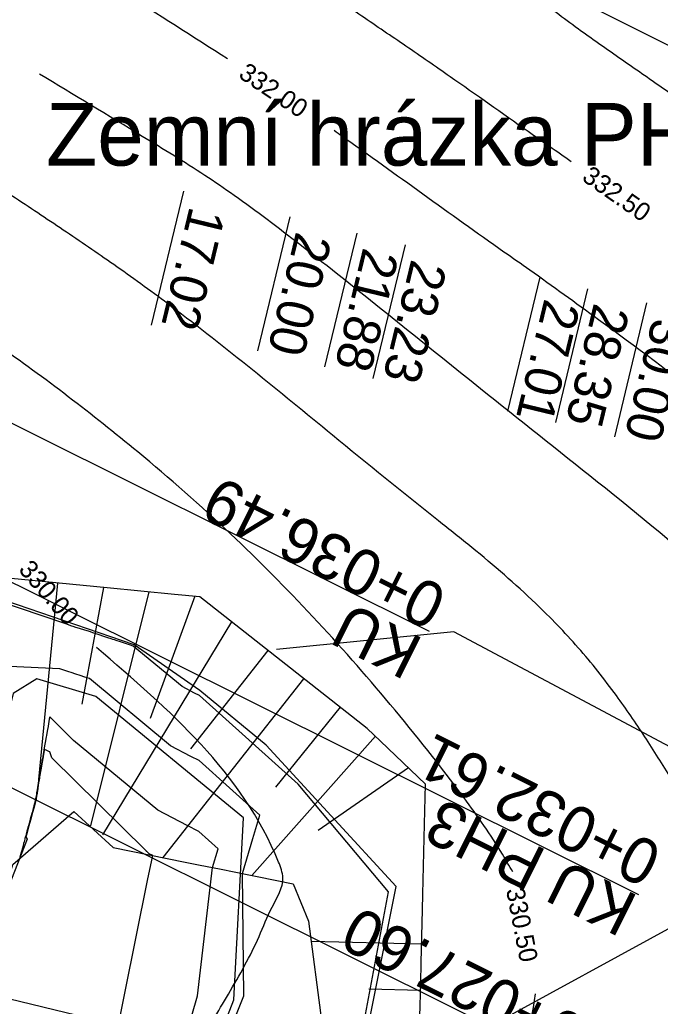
# Model space of a CAD drawing. Extents: x -564043 to -563833, y -1163561 to -1163412.
# Drawn here: x -563886.88 to -563869.43, y -1163493.12 to -1163466.24 of the extents above; entities that cross this region are included whole.
import ezdxf

# ---------------------------------------------------------------- set-up
doc = ezdxf.new("R2010")
doc.units = 0
for name, color, linetype in [('4', 7, 'Continuous'), ('5', 7, 'Continuous'), ('_popis staničení PH3', 7, 'Continuous'), ('_popis staničení T3', 7, 'Continuous'), ('Default', 7, 'Continuous'), ('Line', 7, 'Continuous'), ('Obvod PU', 7, 'Continuous'), ('Vrstva 24', 7, 'Continuous'), ('Vrstva 25', 7, 'Continuous'), ('Vrstva 26', 7, 'Continuous')]:
    doc.layers.add(name, color=color, linetype=linetype)

msp = doc.modelspace()

# ---------------------------------------------------------------- linework, layer by layer
for points in [[(-563900.324, -1163505.882), (-563892.678, -1163503.006), (-563888.735, -1163501.906), (-563886.271, -1163502.018), (-563883.536, -1163500.684), (-563878.095, -1163497.234), (-563876.621, -1163489.849), (-563880.163, -1163485.998), (-563881.977, -1163484.515), (-563883.765, -1163483.269), (-563890.133, -1163481.092), (-563891.974, -1163485.382), (-563895.143, -1163493.304), (-563898.704, -1163502.458), (-563900.439, -1163505.855)], [(-563887.058, -1163484.593), (-563887.855, -1163487.81), (-563890.21, -1163493.633), (-563891.581, -1163498.253), (-563891.461, -1163499.576), (-563890.275, -1163499.82), (-563886.599, -1163499.649), (-563882.84, -1163497.558), (-563881.049, -1163492.941), (-563880.784, -1163487.979), (-563884.81, -1163484.679), (-563886.418, -1163484.198)]]:
    msp.add_lwpolyline(points, close=True)
for points in [[(-563878.137, -1163496.97), (-563876.837, -1163490), (-563879.296, -1163487.066), (-563881.987, -1163484.651), (-563882.119, -1163484.582), (-563882.455, -1163484.408), (-563883.788, -1163483.304), (-563883.864, -1163483.279), (-563884.159, -1163483.181), (-563884.226, -1163483.159), (-563884.302, -1163483.134), (-563884.34, -1163483.121), (-563884.386, -1163483.106), (-563884.482, -1163483.074), (-563884.592, -1163483.038), (-563884.718, -1163482.996), (-563884.865, -1163482.947), (-563884.978, -1163482.91), (-563885.376, -1163482.786), (-563885.4, -1163482.777), (-563885.486, -1163482.747), (-563885.596, -1163482.707), (-563890.151, -1163481.173)], [(-563866.782, -1163487.32), (-563875.054, -1163482.917), (-563879.887, -1163483.398)], [(-563882.19, -1163496.364), (-563880.778, -1163492.835), (-563880.808, -1163489.502), (-563880.527, -1163488.546), (-563880.34, -1163487.91), (-563881.995, -1163486.424), (-563882.215, -1163486.31), (-563882.772, -1163486.021), (-563884.984, -1163484.19), (-563885.111, -1163484.148), (-563885.233, -1163484.108), (-563885.348, -1163484.069), (-563885.478, -1163484.026), (-563885.544, -1163484.004), (-563885.623, -1163483.978), (-563885.788, -1163483.923), (-563887.164, -1163483.863), (-563888.153, -1163487.579), (-563890.867, -1163493.518)], [(-563883.008, -1163496.199), (-563882.04, -1163492.836), (-563881.625, -1163489.337), (-563881.476, -1163488.829), (-563882.005, -1163488.354), (-563882.32, -1163488.191), (-563883.117, -1163487.777), (-563885.412, -1163485.878), (-563885.848, -1163485.443), (-563886.064, -1163485.228), (-563886.076, -1163485.297), (-563886.076, -1163485.299), (-563886.085, -1163485.349), (-563886.086, -1163485.357), (-563886.119, -1163485.544), (-563886.123, -1163485.565), (-563886.154, -1163485.739), (-563886.159, -1163485.771), (-563886.188, -1163485.934), (-563886.195, -1163485.977), (-563886.222, -1163486.129), (-563886.225, -1163486.143), (-563886.233, -1163486.193), (-563886.255, -1163486.313), (-563886.255, -1163486.317), (-563886.275, -1163486.425), (-563886.283, -1163486.475), (-563886.288, -1163486.503), (-563886.291, -1163486.518), (-563886.312, -1163486.636), (-563886.324, -1163486.708), (-563886.339, -1163486.796), (-563886.352, -1163486.873), (-563886.356, -1163486.898), (-563886.367, -1163486.965), (-563886.38, -1163487.043), (-563886.387, -1163487.088), (-563886.417, -1163487.278), (-563886.42, -1163487.295), (-563886.422, -1163487.306), (-563886.427, -1163487.341), (-563886.437, -1163487.403), (-563886.447, -1163487.469), (-563886.478, -1163487.59), (-563886.495, -1163487.654), (-563886.499, -1163487.669), (-563886.517, -1163487.732), (-563886.546, -1163487.835), (-563886.579, -1163487.957), (-563886.595, -1163488.016), (-563886.628, -1163488.14), (-563886.644, -1163488.198), (-563886.656, -1163488.242), (-563886.661, -1163488.262), (-563886.683, -1163488.343), (-563886.693, -1163488.379), (-563886.719, -1163488.477), (-563886.73, -1163488.518), (-563886.738, -1163488.548), (-563886.742, -1163488.561), (-563886.761, -1163488.632), (-563886.775, -1163488.684), (-563886.791, -1163488.742), (-563886.826, -1163488.871), (-563886.84, -1163488.923), (-563886.875, -1163489.052), (-563886.889, -1163489.104)], [(-563884.64, -1163495.87), (-563883.396, -1163489.693), (-563883.258, -1163489.008), (-563883.35, -1163488.961), (-563883.403, -1163488.916), (-563883.413, -1163488.906), (-563883.424, -1163488.896), (-563883.429, -1163488.891), (-563883.454, -1163488.866), (-563886.003, -1163486.346), (-563886.061, -1163486.188), (-563886.092, -1163486.174), (-563886.139, -1163486.152), (-563886.207, -1163486.12), (-563886.209, -1163486.131), (-563886.213, -1163486.15), (-563886.213, -1163486.152), (-563886.242, -1163486.315), (-563886.242, -1163486.316), (-563886.269, -1163486.463), (-563886.271, -1163486.477), (-563886.278, -1163486.515), (-563886.279, -1163486.52), (-563886.307, -1163486.681), (-563886.312, -1163486.71), (-563886.334, -1163486.831), (-563886.339, -1163486.866), (-563886.345, -1163486.9), (-563886.36, -1163486.992), (-563886.366, -1163487.027), (-563886.376, -1163487.09), (-563886.4, -1163487.252), (-563886.405, -1163487.28), (-563886.409, -1163487.304), (-563886.409, -1163487.308), (-563886.417, -1163487.357), (-563886.421, -1163487.379), (-563886.435, -1163487.472), (-563886.478, -1163487.642), (-563886.482, -1163487.657), (-563886.488, -1163487.679), (-563886.492, -1163487.693), (-563886.532, -1163487.838), (-563886.579, -1163488.011), (-563886.581, -1163488.02), (-563886.629, -1163488.196), (-563886.63, -1163488.201), (-563886.647, -1163488.265), (-563886.647, -1163488.266), (-563886.678, -1163488.381), (-563886.679, -1163488.383), (-563886.713, -1163488.512), (-563886.706, -1163488.522), (-563886.68, -1163488.561), (-563886.68, -1163488.562), (-563886.68, -1163488.562), (-563886.679, -1163488.563), (-563889.53, -1163495.82)], [(-563889.53, -1163495.82), (-563888.841, -1163493.998), (-563888.841, -1163493.998), (-563888.841, -1163493.998), (-563887.797, -1163491.659), (-563887.07, -1163489.251), (-563885.406, -1163487.811), (-563884.336, -1163488.791), (-563884.336, -1163488.791), (-563884.336, -1163488.791), (-563883.356, -1163488.989), (-563882.375, -1163489.186), (-563882.009, -1163489.26), (-563881.395, -1163489.384), (-563880.687, -1163489.526), (-563880.415, -1163489.581), (-563879.434, -1163489.779), (-563879.009, -1163490.8), (-563878.655, -1163493.506)]]:
    msp.add_lwpolyline(points)
at = {"layer": '5'}
for p, q in [((-563897.15, -1163506.247), (-563862.812, -1163487.513)), ((-563904.23, -1163488.796), (-563873.359, -1163496.24))]:
    msp.add_line(p, q, dxfattribs=at)
at = {"layer": '_popis staničení PH3'}
for points in [[(-563889.152, -1163476.21), (-563875.726, -1163482.9)], [(-563890.882, -1163479.681), (-563870.022, -1163490.074)], [(-563893.116, -1163484.167), (-563871.756, -1163494.81)]]:
    msp.add_lwpolyline(points, dxfattribs=at)
at = {"layer": '_popis staničení T3'}
for p, q in [((-563883.288, -1163474.558), (-563882.408, -1163470.913)), ((-563880.392, -1163475.256), (-563879.513, -1163471.611)), ((-563878.565, -1163475.697), (-563877.686, -1163472.051)), ((-563877.254, -1163476.013), (-563876.375, -1163472.368)), ((-563873.58, -1163476.899), (-563872.701, -1163473.253)), ((-563872.278, -1163477.213), (-563871.399, -1163473.567)), ((-563870.67, -1163477.6), (-563869.791, -1163473.955))]:
    msp.add_line(p, q, dxfattribs=at)
at = {"layer": 'Default'}
msp.add_lwpolyline([(-563875.979, -1163493.391), (-563875.957, -1163492.484), (-563875.943, -1163491.921), (-563875.909, -1163490.489), (-563875.899, -1163490.06), (-563875.853, -1163488.158), (-563875.827, -1163487.061), (-563877.051, -1163485.894), (-563877.417, -1163485.546), (-563881.974, -1163481.961), (-563882.667, -1163481.894), (-563884.497, -1163481.718), (-563886.832, -1163481.493), (-563890.151, -1163481.173)], dxfattribs=at)
at = {"layer": 'Line'}
for p, q in [((-563886.362, -1163486.934), (-563885.847, -1163481.588)), ((-563884.602, -1163481.708), (-563885.193, -1163484.881)), ((-563884.948, -1163488.198), (-563883.358, -1163481.827)), ((-563882.114, -1163481.947), (-563883.329, -1163485.273)), ((-563884.614, -1163488.443), (-563881.102, -1163482.646)), ((-563880.12, -1163483.419), (-563882.231, -1163486.103)), ((-563882.972, -1163489.066), (-563879.137, -1163484.192)), ((-563878.155, -1163484.965), (-563879.913, -1163487.147)), ((-563880.557, -1163489.552), (-563877.192, -1163485.76)), ((-563876.287, -1163486.623), (-563878.747, -1163488.324)), ((-563875.931, -1163491.424), (-563878.937, -1163491.352)), ((-563877.367, -1163492.64), (-563875.961, -1163492.674))]:
    msp.add_line(p, q, dxfattribs=at)
at = {"layer": 'Obvod PU'}
msp.add_lwpolyline([(-563885.14, -1163462.32), (-563874.2, -1163464.42), (-563869.21, -1163466.93)], dxfattribs=at)
at = {"layer": 'Vrstva 24'}
for points in [[(-563881.219, -1163467.306), (-563886.923, -1163463.69), (-563888.12, -1163462.966), (-563888.746, -1163462.613), (-563889.58, -1163462.16), (-563890.418, -1163461.713), (-563891.255, -1163461.265), (-563892.088, -1163460.81), (-563893.666, -1163459.845), (-563894.43, -1163459.321), (-563895.185, -1163458.779), (-563896.456, -1163457.801), (-563897.673, -1163456.767), (-563898.845, -1163455.679), (-563899.977, -1163454.537), (-563900.905, -1163453.498), (-563901.733, -1163452.383), (-563902.044, -1163451.876), (-563902.327, -1163451.358), (-563902.78, -1163450.276), (-563904.206, -1163445.764), (-563905.71, -1163441.12)], [(-563862.955, -1163472.882), (-563865.358, -1163470.941), (-563867.276, -1163469.557), (-563868.391, -1163468.776), (-563869.51, -1163468.001), (-563870.628, -1163467.223), (-563871.739, -1163466.436), (-563872.344, -1163465.986), (-563877.172, -1163462.238), (-563879.042, -1163460.73), (-563880.713, -1163459.293), (-563882.35, -1163457.816), (-563883.983, -1163456.336), (-563885.646, -1163454.889), (-563886.028, -1163454.584), (-563886.155, -1163454.491), (-563886.219, -1163454.446), (-563886.25, -1163454.423), (-563886.266, -1163454.411)], [(-563866.364, -1163497.311), (-563866.075, -1163496.511), (-563865.895, -1163495.533), (-563865.845, -1163494.553), (-563865.947, -1163493.507), (-563866.272, -1163492.388), (-563866.563, -1163491.699), (-563866.868, -1163491.02), (-563867.192, -1163490.352), (-563867.536, -1163489.691), (-563869.125, -1163486.92), (-563869.85, -1163485.772), (-563870.624, -1163484.653), (-563871.666, -1163483.346), (-563872.824, -1163482.142), (-563874.562, -1163480.618), (-563875.472, -1163479.893), (-563878.363, -1163477.556), (-563882.755, -1163474.046), (-563884.234, -1163472.969), (-563885.61, -1163472.026), (-563886.998, -1163471.1), (-563889.83, -1163469.34), (-563892.347, -1163467.891)], [(-563852.947, -1163500.287), (-563852.983, -1163499.934), (-563853.278, -1163497.907), (-563853.324, -1163497.501), (-563853.384, -1163496.604), (-563853.408, -1163496.155), (-563853.449, -1163495.707), (-563853.76, -1163494.797), (-563854.364, -1163493.737), (-563856.816, -1163489.636), (-563859.313, -1163485.439), (-563859.915, -1163484.694), (-563860.397, -1163484.207), (-563862.509, -1163482.09), (-563867.011, -1163477.664), (-563868.116, -1163476.702), (-563871.116, -1163474.41), (-563872.986, -1163473.06), (-563873.689, -1163472.566), (-563878.103, -1163469.411), (-563878.316, -1163469.26)]]:
    msp.add_spline(points, degree=3, dxfattribs=at)
at = {"layer": 'Vrstva 25'}
msp.add_spline([(-563905.141, -1163510.37), (-563904.922, -1163510.229), (-563901.706, -1163508.177), (-563898.297, -1163505.868), (-563895.6, -1163504.013), (-563893.249, -1163502.324), (-563892.081, -1163501.469), (-563890.919, -1163500.608), (-563889.757, -1163499.746), (-563888.589, -1163498.892), (-563887.491, -1163498.145), (-563886.364, -1163497.441), (-563885.229, -1163496.747), (-563884.107, -1163496.03), (-563883.48, -1163495.59), (-563883.181, -1163495.349), (-563882.893, -1163495.092), (-563882.209, -1163494.336), (-563881.626, -1163493.502), (-563881.193, -1163492.783), (-563880.36, -1163491.213), (-563880.004, -1163490.417), (-563879.711, -1163489.616), (-563879.829, -1163489.186), (-563884.789, -1163483.345)], degree=3, dxfattribs=at)
at = {"layer": 'Vrstva 26'}
for points in [[(-563871.856, -1163470.105), (-563873.031, -1163469.285), (-563875.156, -1163467.789), (-563876.357, -1163466.959), (-563877.564, -1163466.138), (-563878.77, -1163465.315), (-563879.967, -1163464.48), (-563881.537, -1163463.354), (-563887.187, -1163459.271), (-563890.237, -1163457.354), (-563891.792, -1163456.442), (-563893.339, -1163455.518), (-563894.167, -1163455.001), (-563894.589, -1163454.631), (-563894.918, -1163454.179), (-563895.238, -1163453.557), (-563895.54, -1163452.929), (-563896.062, -1163451.643), (-563896.672, -1163449.878), (-563897.273, -1163448.112), (-563898.405, -1163444.558), (-563898.83, -1163443.13)], [(-563873.45, -1163489.454), (-563873.727, -1163488.976), (-563874.776, -1163487.436), (-563876.784, -1163484.893), (-563881.14, -1163480.242), (-563883.664, -1163478.013), (-563887.513, -1163475.075), (-563890.545, -1163473.024), (-563896.225, -1163469.436), (-563897.371, -1163468.706), (-563897.941, -1163468.337), (-563899.477, -1163467.352), (-563904.895, -1163463.746), (-563905.311, -1163463.453)], [(-563859.41, -1163497.306), (-563859.213, -1163496.32), (-563859.173, -1163495.343), (-563859.23, -1163495.062), (-563859.315, -1163494.786), (-563859.559, -1163494.264), (-563860.664, -1163492.33), (-563861.767, -1163490.395), (-563863.612, -1163487.077), (-563864.619, -1163485.435), (-563865.167, -1163484.642), (-563865.744, -1163483.864), (-563868.01, -1163481.46), (-563871.348, -1163478.665), (-563874.529, -1163476.131), (-563879.25, -1163472.365), (-563881.038, -1163471.025), (-563881.839, -1163470.479), (-563883.542, -1163469.415), (-563886.341, -1163467.718)], [(-563906.28, -1163515.803), (-563905.884, -1163515.571), (-563902.883, -1163513.741), (-563899.929, -1163512.038), (-563897.928, -1163511.018), (-563895.553, -1163509.778), (-563893.055, -1163508.246), (-563892.353, -1163507.782), (-563891.657, -1163507.311), (-563890.96, -1163506.841), (-563890.257, -1163506.379), (-563888.16, -1163505.094), (-563886.21, -1163504.031), (-563880.965, -1163501.085), (-563878.454, -1163499.578), (-563877.23, -1163498.772), (-563876.032, -1163497.922), (-563874.901, -1163496.941), (-563873.614, -1163495.651), (-563873.276, -1163495.107), (-563873.154, -1163494.587), (-563873.048, -1163494.066), (-563872.865, -1163493.019), (-563872.827, -1163492.778)]]:
    msp.add_spline(points, degree=3, dxfattribs=at)

# ---------------------------------------------------------------- texts
at = {"layer": '4'}
msp.add_text('Zemní hrázka PH3', height=1.70472, rotation=360, dxfattribs=at).set_placement((-563886.162, -1163470.212))
at = {"layer": '_popis staničení PH3'}
for s, p in [('0+036.49', (-563875.169, -1163481.781)), ('KU ', (-563875.838, -1163483.124)), ('0+032.61', (-563869.311, -1163488.787)), ('KU PH3 ', (-563869.98, -1163490.129)), ('0+027.60', (-563871.381, -1163493.5))]:
    msp.add_text(s, height=1.25, rotation=153.5152, dxfattribs=at).set_placement(p)
at = {"layer": '_popis staničení T3'}
for s, p in [('17.02', (-563882.243, -1163471.291)), ('20.00', (-563879.345, -1163471.983)), ('21.88', (-563877.517, -1163472.418)), ('23.23', (-563876.206, -1163472.736)), ('27.01', (-563872.578, -1163473.81)), ('28.35', (-563871.229, -1163473.928)), ('30.00', (-563869.624, -1163474.327))]:
    msp.add_text(s, height=1, rotation=256.4433, dxfattribs=at).set_placement(p)
at = {"layer": 'Vrstva 25'}
for s, rotation, p in [('332.00', 326.0566, (-563880.949, -1163467.793)), ('332.50', 324.9898, (-563871.593, -1163470.595)), ('330.00', 310.6836, (-563886.936, -1163481.23)), ('330.50', 280.9781, (-563873.634, -1163489.939))]:
    msp.add_text(s, height=0.5, rotation=rotation, dxfattribs=at).set_placement(p)

doc.saveas('drawing.dxf')
